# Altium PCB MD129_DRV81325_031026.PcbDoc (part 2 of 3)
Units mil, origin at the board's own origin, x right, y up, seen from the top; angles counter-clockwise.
Board outline 4300.91 x 4001.52 mil, 4 copper layers (Top Layer, GND, PWR, Bottom Layer), stack 92.668 mil thick; 211 components, 89 nets, 489 pads, 980 vias.
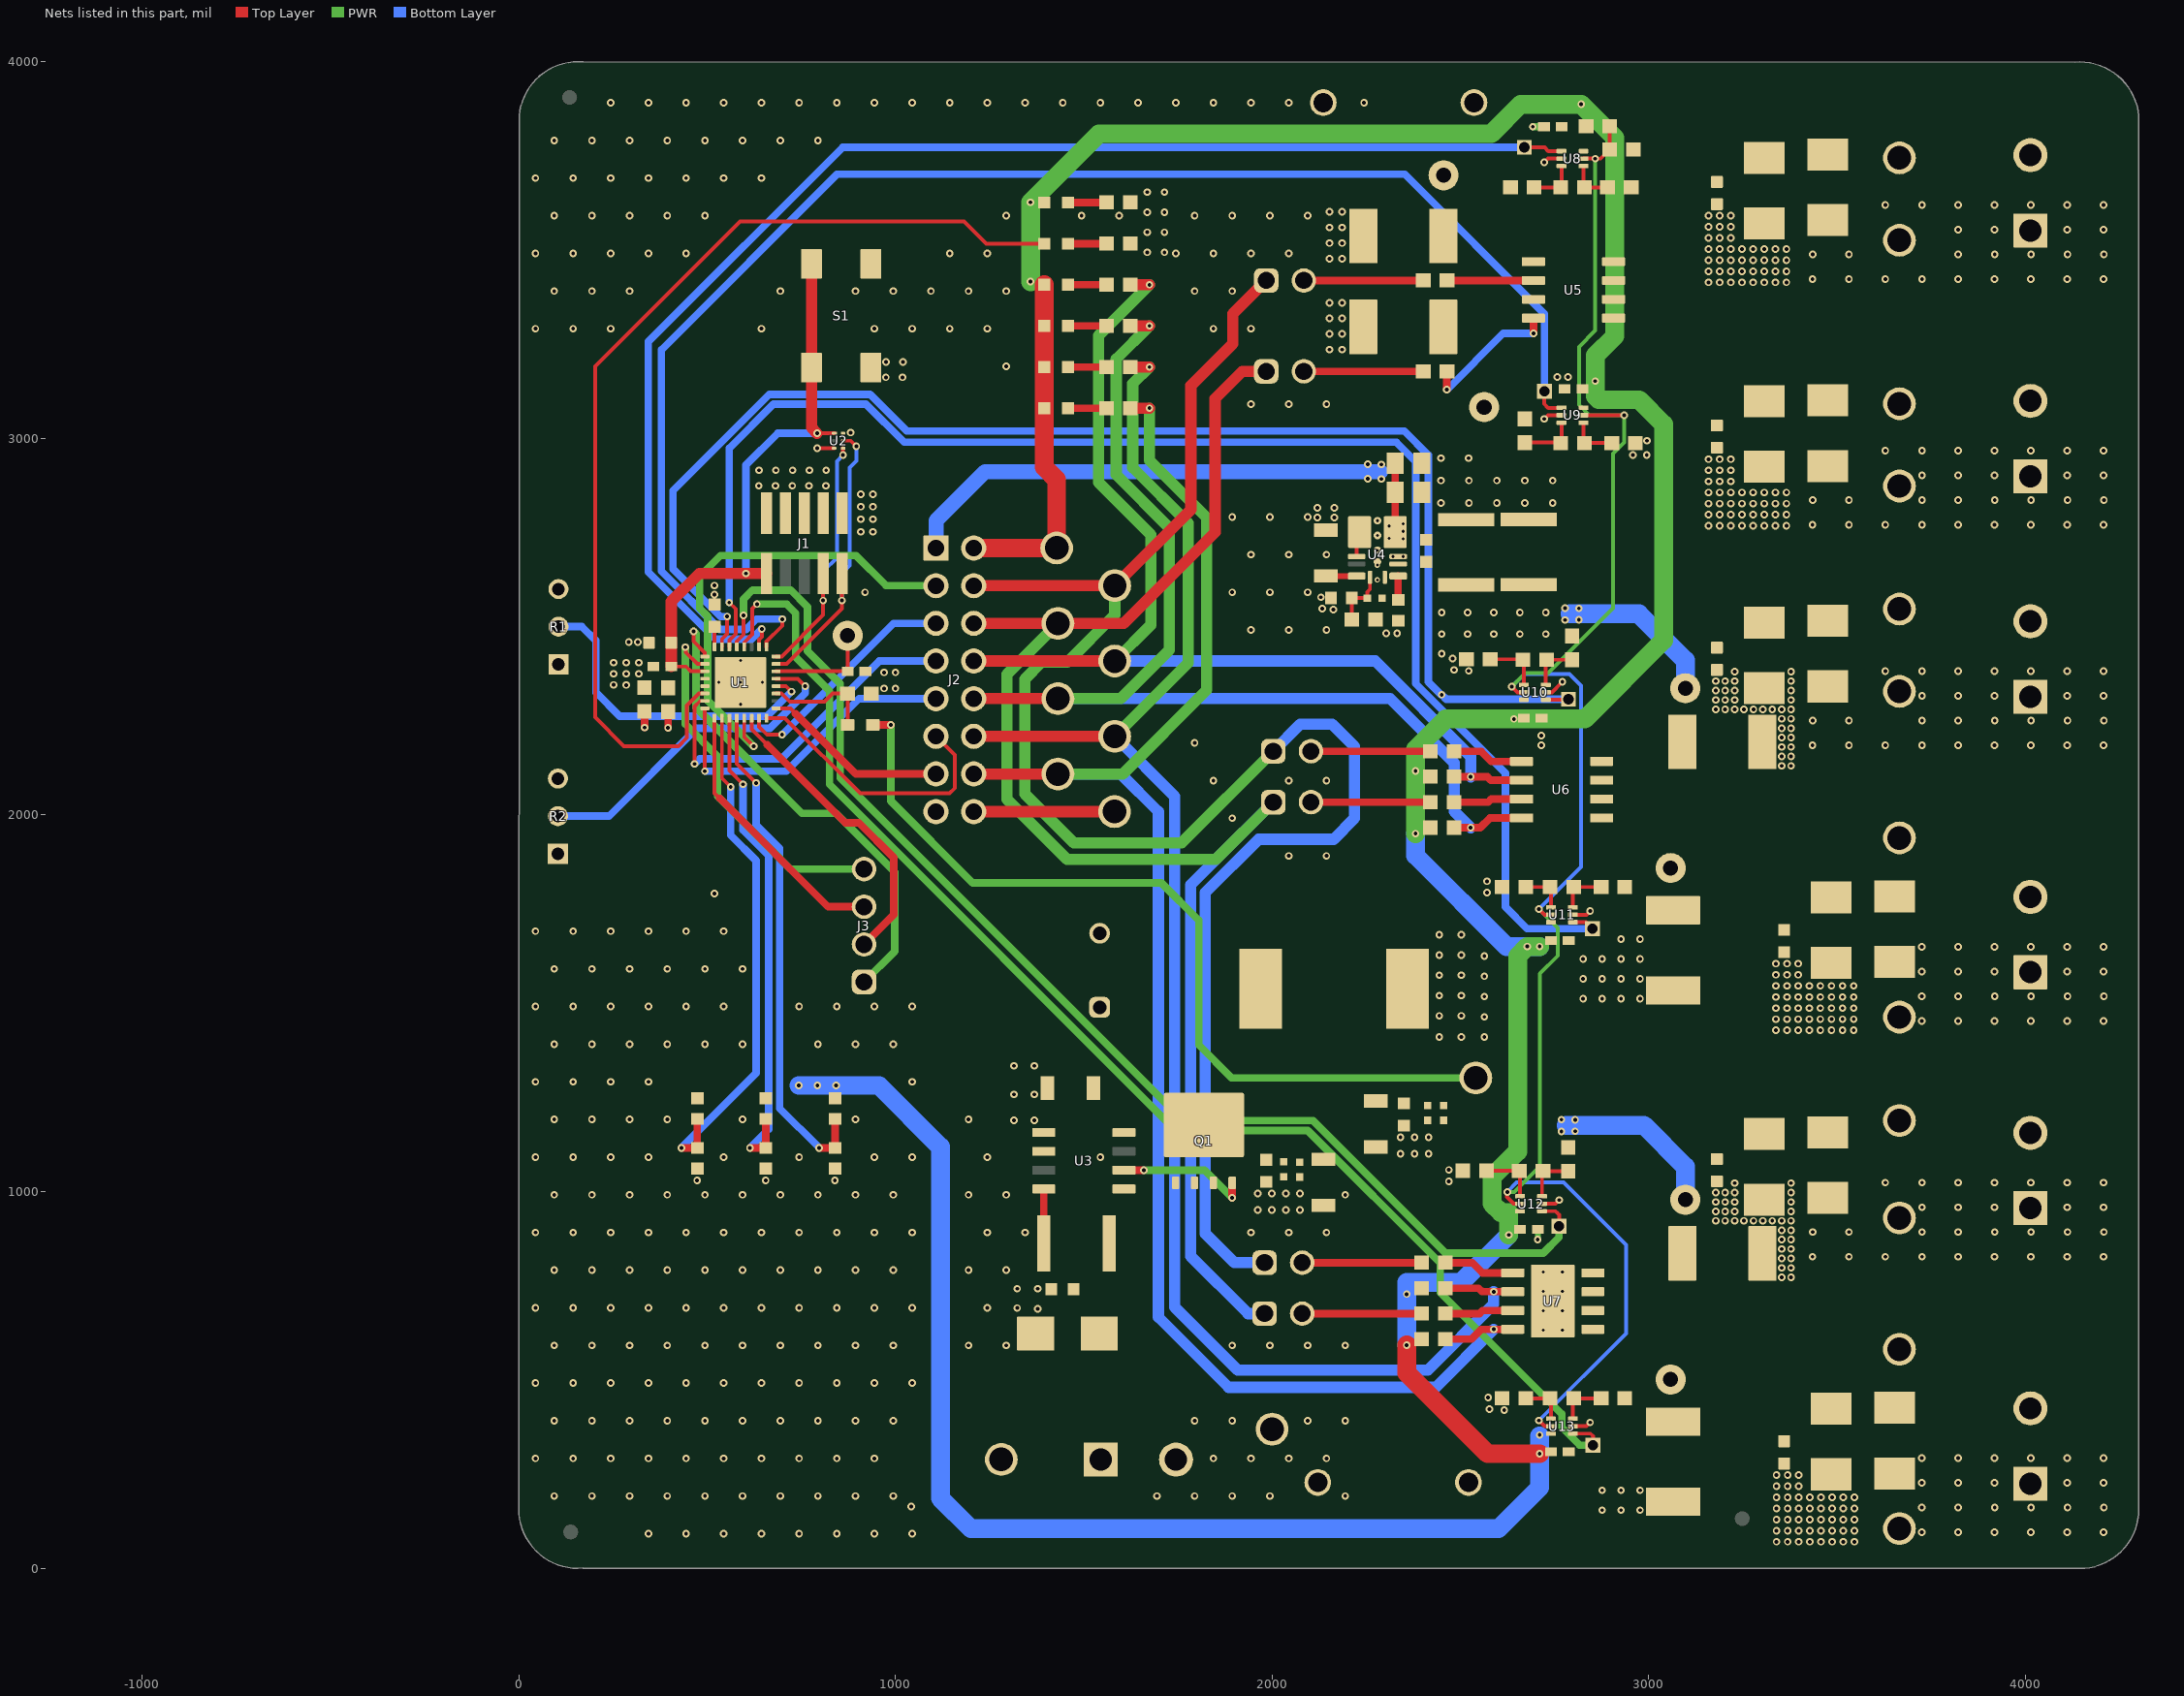
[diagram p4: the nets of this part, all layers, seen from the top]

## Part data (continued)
R14 R15 R16 R17 R18: library part CMP-0025912-5, "RES, 330, 5%, 0.1 W, 0603", Manufacturer=Yageo, Power_W=100mW, Supplier Part Number 1=311-330GRCT-ND, TempCo="100 ppm/C", Tolerance_%=5%, Value2=0.1W, Value_Code=330R, ValueDisplayed=330
R19 R20 R21 R22 R23 R24: library part CMP-0088493-1, "10 mOhms ±0.5% 2W Chip Resistor 2512 (6432 Metric) Automotive AEC-Q200, Current Sense, Moisture Resistant Metal Film", Digikey Part Number=273-PCS2512DR0100ETCT-ND, Manufacturer=Ohmite, Mouser Part Number=588-PCS2512DR0100ET, Operating Temperature Range="-55°C to +170°C", Power_W=2W, TempCo=50ppm/°C, Tolerance_%=0%
R25 R26: library part CMP-0022902-5, "RES, 200, 1%, 0.1 W, 0603", Manufacturer=Yageo, Power_W=100mW, Supplier Part Number 1=311-200HRCT-ND, TempCo="100 ppm/C", Tolerance_%=1%, Value2=0.1W, Value_Code=200R, ValueDisplayed=200
R27 R28 R31 R32 R36 R37 R42 R43 R44 R45 R50 R51: library part CMP-0025874-4, "RES, 0, 5%, 0.1 W, AEC-Q200 Grade 0, 0603", Manufacturer=Panasonic, Power_W=100mW, Supplier Part Number 1=P0.0GCT-ND, TempCo="600 ppm/C", Tolerance_%=5%, Value2=0.1W, Value_Code=0000, ValueDisplayed=0
R34: library part CMP-0022933-5, "RES, 23.2 k, 1%, 0.1 W, 0603", Manufacturer=Yageo, Power_W=100mW, Supplier Part Number 1=311-23.2KHRCT-ND, TempCo="100 ppm/C", Tolerance_%=1%, Value2=0.1W, Value_Code=23k2, ValueDisplayed=23.2k
R35: library part CMP-0025886-3, "RES, 10 k, 5%, 0.1 W, 0603", Manufacturer=Yageo, Power_W=100mW, Supplier Part Number 1=311-10KGRCT-ND, TempCo="100 ppm/C", Tolerance_%=5%, Value2=0.1W, Value_Code=10k0, ValueDisplayed=10k
R39 R41 R47 R49: library part CMP-0023155-5, "RES, 4.99 k, 1%, 0.1 W, 0603", Manufacturer=Yageo, Power_W=100mW, Supplier Part Number 1=311-4.99KHRCT-ND, TempCo="100 ppm/C", Tolerance_%=1%, Value2=0.1W, Value_Code=4k99, ValueDisplayed=4.99k
S1: library part CMP-0097347-1, "Tactile Switch SPST-NO Top Actuated Surface Mount", Coil Resistance_ohm=100mΩ, Contact Current Rating=50mA, Digikey Part Number=732-7022-1-ND, Manufacturer="Wurth Electronics", Mouser Part Number=710-430481025816, Operating Force=160gf, Operating Temperature Range="-40°C to +85°C"
SH1 SH2: library part CMP-0075110-1, "1mm Uninsulated Shorting Plug, 10.16mm spacing, TH", Manufacturer=Harwin, PartNumber=D3082-05, Supplier Part Number 1=952-1873-ND
SH1-J2-1 SH2-J2 SH3-J2 SH4-J2 SH5-J2 SH6-J2 SH7-J2 SH8-J2 SH-J5 SH-J6 SH-J7 SH-J8 SH-J9 SH-J10: library part CMP-0003761-2, "Shunt, 2.54mm, Gold, Black", Manufacturer="Wurth Elektronik", Supplier Part Number 1=732-2678-ND
TP1 TP12 TP13 TP14 TP15 TP17 TP18: library part CMP-0055139-2, "Test Point, Miniature, White, TH", Color=White, Manufacturer="Keystone Electronics", Supplier Part Number 1=36-5002-ND
TP2: library part CMP-0055150-1, "Test Point, Multipurpose, Orange, TH", Color=Orange, Manufacturer=Keystone, Supplier Part Number 1=36-5013-ND
TP3 TP4 TP5 TP6 TP7 TP8 TP19 TP21 TP23 TP25 TP27 TP29: library part CMP-0055149-2, "Test Point, Multipurpose, White, TH", Color=White, Manufacturer="Keystone Electronics", Supplier Part Number 1=36-5012-ND
TP9 TP11: library part CMP-0055148-2, "Test Point, Multipurpose, Black, TH", Color=Black, Manufacturer="Keystone Electronics", Supplier Part Number 1=36-5011-ND
TP10 TP16 TP20 TP22 TP24 TP26 TP28 TP30: library part CMP-0055147-2, "Test Point, Multipurpose, Red, TH", Color=Red, Manufacturer="Keystone Electronics", Supplier Part Number 1=36-5010-ND
U1: library part CMP-0093963-1, "Mixed-Signal Microcontrollers with CAN-FD Interface, VQFN32", Frequency_Fixed=80MHz, Manufacturer="Texas Instruments", Max Supply Voltage=3.6V, Min Supply Voltage=1.62V, Operating Temperature Range="-40°C to +125°C"
U2: library part CMP-0043115-2, "ESD-Protection Array for High-Speed Data Interfaces, 4 Channels, -40 to +85 degC, 6-pin SON (DRY), Green (RoHS & no Sb/Br)", Breakdown Voltage(Min)(V)=6, IO Capacitance(Typ)(pF)=1.6, IO Leakage Current(nA)=1, Manufacturer="Texas Instruments"
U3: library part CMP-0125797-1, Manufacturer="Texas Instruments", Operating Temperature Range=to, Part Number=LM74700D-Q1
U4: library part CMP-0094617-1, "3-V to 65-V Input, 1-V to 13-V Output, 600-mA Synchronous Buck Converter Power Module in a HotRod QFN Package", Manufacturer="Texas Instruments", Max Supply Voltage=65V, Min Supply Voltage=3.6V, Nominal Supply Current=17-18uA, Operating Temperature Range="-40°C to +125°C", Output Voltage=1-13V, Switching Frequency=200-2200kHz
U5: library part CMP-0127644-1, "Dual Channel Protected Low side switch, SOIC8", Manufacturer="Texas Instruments", Max Supply Voltage=5.5V, Min Supply Voltage=3V, Operating Temperature Range="-40°C to +150°C"
U6: library part CMP-0127803-1, Manufacturer="Texas Instruments", Operating Temperature Range=to
U7: library part CMP-0127624-1, "Dual Channel Protected Low side switch, HSOIC8", Manufacturer="Texas Instruments", Max Supply Voltage=5.5V, Min Supply Voltage=3V, Operating Temperature Range="-40°C to +150°C"
U8 U9 U10 U11 U12 U13: library part CMP-0085242-1, "Bidirectional, Precision Low- and High-Side Voltage Output, Current-Sense Amplifier, DRL0006A (SOT-5X3-6)", Alternate Manufacturer="Texas Instruments", Alternate PartNumber=INA185A2IDRLT
ZZ1: library part CMP-0003616-3
ZZ2: library part CMP-0077236-1
ZZ3: library part CMP-0077237-1
ZZ4: library part CMP-0077238-1

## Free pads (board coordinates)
  rect 39.37x39.37 hole 27.56: 7(2669.59,3772.78) 7(2722.57,3124.75) 7(2761.65,908.17) 7(2786.75,2307.25) 7(2850.31,1698.27) 7(2851.77,326.17)

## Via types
v1: diameter 20, hole 10, Top Layer to Bottom Layer, tented both sides, 955 vias
v2: diameter 19.68, hole 7.87, Top Layer to Bottom Layer, tented both sides, 16 vias
v3: diameter 19.68, hole 7.87, Top Layer to Bottom Layer, 5 vias
v4: diameter 14, hole 8, Top Layer to Bottom Layer, tented both sides, 4 vias

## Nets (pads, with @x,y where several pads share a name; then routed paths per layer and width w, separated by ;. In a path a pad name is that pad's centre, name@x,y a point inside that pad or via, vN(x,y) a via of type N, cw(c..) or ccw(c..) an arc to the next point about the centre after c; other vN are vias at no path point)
3V3: C24.2 C27.2 C30.2 C33.2 C36.2 C39.2 D1.2 D3.2 D4.2 D5.2 D6.2 J2.2 R7.1 R8.1 R9.1 R25.2 R39.1 R41.1 R47.1 R49.1 TP2.1 U8.6 U9.6 U10.6 U11.6 U12.6 U13.6 | length 10880.1
  Top Layer w50: J2.2@1207.37,2708.86 TP2.1@1427.69,2708.86 1427.69,2890.62 1394.69,2923.62 D6.2@1394.69,3080.28 D5.2@1394.69,3189.52 D4.2@1394.69,3298.75 D3.2@1394.69,3407.98 ; v1(2357.06,592.21) 2357.06,518.15 2571.52,303.69 v1(2709.96,303.69)
  PWR w50: v1(1358.33,3416.4) v1(1358.33,3627.1) 1540.24,3809.01 2581.43,3809.01 2659.7,3887.27 v1(2820.33,3887.27) 2909.62,3797.99 2909.62,3271.72 2857.73,3219.82 v1(2857.73,3151.98) 2857.73,3112.17 2867.4,3102.49 2974.02,3102.49 3038.9,3037.62 3038.9,2463.75 2830.2,2255.04 v1(2641.72,2255.04) 2460.64,2255.04 2380.43,2174.83 v1(2380.43,2116.98) v1(2380.43,1950.37) ; v1(2628.05,884.62) 2628.05,944.1 2607.38,944.1 2583.35,968.13 2583.35,1038.34 2651.48,1106.46 2651.48,1624.59 v1(2677.44,1650.55) v1(2709.96,1650.55)
  Bottom Layer w50: v1(743.05,1281.62) v1(792.65,1281.62) v1(842.25,1281.62) 956.02,1281.62 1119.17,1118.47 1119.17,185.67 1200.35,104.49 2600.62,104.49 2709.96,213.83 v1(2709.96,303.69) v1@2709.96,350.82 ; v1(2357.06,592.21) v1(2357.06,727.51) 2357.06,758.81 2502.24,758.81 v1(2628.05,884.62) ; v1(2380.43,1950.37) 2380.43,1892.37 2622.25,1650.55 v1(2677.44,1650.55) v1(2709.96,1650.55)
  other v1: 2709.96,353.43
BSL_INVOKE: R4.2 TP1.1 U1.22 | length 284.5
  Top Layer w10: U1.22@682.82,2381.47 R4.2@872.65,2381.47 TP1.1@872.65,2476.13
BUCK_3V3: C4.1 C5.1 C21.2 C22.1 C23.1 J1.1 J2.1 R1.1 R2.1 R3.2 R34.2 R35.2 U1.4 U2.6 U4.4 | length 1489.7
  Top Layer w20: U4.4@2326.57,2751.21 C22.1@2326.57,2857.12 C23.1@2326.57,2933.66
  Bottom Layer w40: J2.1@1107.37,2708.86 1107.37,2781.57 1237.75,2911.94 2287.88,2911.94
  other v1: 251.3,2345.44 284.7,2345.13 251.3,2374.74 284.7,2374.74 318.09,2374.74 251.3,2404.36 284.7,2404.36 318.09,2404.36 2302.75,2482.53 2331.64,2482.53 907.39,2751.91 939.99,2751.91 907.39,2785.26 939.99,2785.26 907.39,2818.61 939.99,2818.61 907.39,2851.95 939.99,2851.95 2289.83,2892.22 2253.92,2893.1 2253.92,2931.5 2289.83,2930.85 880.84,3015.56
  other v2: 2347.44,2733.49 2310.04,2735.07 2347.44,2753.18 2310.04,2767.35 2347.44,2772.86
DEV_ID1: R7.2 R10.1 U1.10 | length 1379.9
  Top Layer w10: U1.10@539.12,2257.46 539.12,2097.51 v1(562.1,2074.53)
  Top Layer w20: v1(431.48,1116.03) R10.1@473.51,1116.03 R7.2@473.51,1192.68
  Bottom Layer w20: v1(431.48,1116.03) 629.88,1314.42 629.88,1878.71 562.24,1946.35 562.24,2074.39 v1(562.1,2074.53)
DEV_ID2: R8.2 R11.1 U1.11 | length 1323.7
  Top Layer w10: U1.11@558.81,2257.46 558.81,2117.72 v1(595.14,2081.38)
  Top Layer w20: v1(613.46,1116.03) R11.1@655.49,1116.03 R8.2@655.49,1192.68
  Bottom Layer w20: v1(595.14,2081.38) 595.14,1960.11 662.91,1892.33 662.91,1165.48 v1(613.46,1116.03)
DEV_ID3: R9.2 R12.1 U1.12 | length 1350.7
  Top Layer w10: U1.12@578.49,2257.46 578.49,2136.36 v1(629.77,2085.08)
  Top Layer w20: v1(797.25,1116.03) R12.1@839.28,1116.03 R9.2@839.28,1192.68
  Bottom Layer w20: v1(629.77,2085.08) 629.77,1973.36 692.32,1910.82 692.32,1220.96 v1(797.25,1116.03)
GND: C1.1 C3.1 C4.2 C5.2 C6.1 C7.2 C8.1 C9.1 C10.1 C11.1 C12.1 C13.1 C14.1 C15.1 C16.2 C17.1 C18.1 C19.1 C20.1 C22.2 C23.2 C24.1 C26.1 C27.1 C29.1 C30.1 C32.1 C33.1 C35.1 C36.1 C38.1 C39.1 C41.1 D7.2 D8.1 D9.1 D10.1 D11.1 D12.1 D13.1 J1.3 J1.5 J1.7 J1.9 J2.15 J2.16 J4.2 R1.3 R2.3 R4.1 R5.1 R10.2 R11.2 R12.2 R13.1 R14.1 R19.1 R20.1 R21.1 R22.1 R23.1 R24.1 R26.1 R27.1 R32.1 R33.1 R36.1 R42.1 R44.1 R50.1 S1.3 S1.4 SH1.1 SH1.2 SH2.1 SH2.2 TP9.1 TP11.1 U1.5 U1.33 U2.3 U3.1 U4.10 U4.11 U7.9 U8.2 U9.2 U10.2 U11.2 U12.2 U13.2 | length 866.5
  Top Layer w10: v1(792.05,2974.11) U2.3@836.91,2974.11 ; U12.2@2716.35,967.51 2752.23,967.51 v1(2762.08,977.36) ; v1(2722.34,3051.64) 2732.19,3061.49 U9.2@2768.08,3061.49 ; v1(2722.34,3733.29) 2732.19,3743.14 U8.2@2768.08,3743.14 ; U10.2@2726.35,2325.67 2742.61,2325.67 v1(2770.34,2353.4) ; U13.2@2798.26,376.84 2834.14,376.84 v1(2843.99,386.69) ; U11.2@2798.26,1735 2834.14,1735 v1(2843.99,1744.86)
  Top Layer w20: v1(333.52,2232.07) C4.2@333.52,2275.37 ; v1(396.02,2231.37) C5.2@396.02,2274.67
  Top Layer w30: J2.16@1207.37,2008.86 TP9.1@1581.39,2008.86
  PWR w15: v1(2704.66,872.79) 2705.32,873.45 2705.32,899.15
  PWR w20: v1(2691.76,3827.65) 2691.97,3827.86 2721.49,3827.86
  other v1: 3339,69.96 3368.49,69.96 3397.98,69.96 3427.47,69.96 3456.96,69.96 3486.46,69.96 3515.95,69.96 3545.44,69.96 343.88,91.29 443.88,91.29 543.88,91.29 643.88,91.29 743.88,91.29 843.88,91.29 943.88,91.29 1043.88,91.29 3339,99.45 3368.49,99.45 3397.98,99.45 3427.47,99.45 3456.96,99.45 3486.46,99.45 3515.95,99.45 3545.44,99.45 3339,128.94 3368.49,128.94 3397.98,128.94 3427.47,128.94 3456.96,128.94 3486.46,128.94 3515.95,128.94 3545.44,128.94 2875.86,153.82 2926.18,153.82 2976.5,153.82 3339,158.43 3368.49,158.43 3397.98,158.43 3427.47,158.43 3456.96,158.43 3486.46,158.43 3515.95,158.43 3545.44,158.43 1041.59,163.28 3339,187.92 3368.49,187.92 3397.98,187.92 3427.47,187.92 3456.96,187.92 3486.46,187.92 3515.95,187.92 3545.44,187.92 93.88,191.29 193.88,191.29 293.88,191.29 393.88,191.29 493.88,191.29 593.88,191.29 693.88,191.29 793.88,191.29 893.88,191.29 993.88,191.29 1693.88,191.29 1793.88,191.29 1893.88,191.29 1993.88,191.29 2193.88,191.29 2875.86,206.6 2926.18,206.6 2976.5,206.6 3339,217.41 3368.49,217.41 3397.98,217.41 3339,246.9 3368.49,246.9 3397.98,246.9 43.88,291.29 143.88,291.29 243.88,291.29 343.88,291.29 443.88,291.29 543.88,291.29 643.88,291.29 743.88,291.29 843.88,291.29 943.88,291.29 1843.88,291.29 1943.88,291.29 2043.88,291.29 2143.88,291.29 93.88,391.29 193.88,391.29 293.88,391.29 393.88,391.29 493.88,391.29 593.88,391.29 693.88,391.29 793.88,391.29 893.88,391.29 993.88,391.29 1793.88,391.29 1893.88,391.29 2093.88,391.29 2193.88,391.29 2616.11,419.83 2576.89,422.23 2573.33,452.67 43.88,491.29 143.88,491.29 243.88,491.29 343.88,491.29 443.88,491.29 543.88,491.29 643.88,491.29 743.88,491.29 843.88,491.29 943.88,491.29 1043.88,491.29 93.88,591.29 193.88,591.29 293.88,591.29 393.88,591.29 493.88,591.29 593.88,591.29 693.88,591.29 793.88,591.29 893.88,591.29 993.88,591.29 1193.88,591.29 1293.88,591.29 1893.88,591.29 1993.88,591.29 2093.88,591.29 2193.88,591.29 1377.2,688.49 1322.98,690.63 43.88,691.29 143.88,691.29 243.88,691.29 343.88,691.29 443.88,691.29 543.88,691.29 643.88,691.29 743.88,691.29 843.88,691.29 943.88,691.29 1043.88,691.29 1243.88,691.29 1322.98,741.87 1377.2,741.87 3352.57,772.29 3377.57,772.29 93.88,791.29 193.88,791.29 293.88,791.29 393.88,791.29 493.88,791.29 593.88,791.29 693.88,791.29 793.88,791.29 893.88,791.29 993.88,791.29 1193.88,791.29 1293.88,791.29 3352.57,797.29 3377.57,797.29 3352.57,822.29 3377.57,822.29 3352.57,847.29 3377.57,847.29 3352.57,872.29 3377.57,872.29 43.88,891.29 143.88,891.29 243.88,891.29 343.88,891.29 443.88,891.29 543.88,891.29 643.88,891.29 743.88,891.29 843.88,891.29 943.88,891.29 1043.88,891.29 1243.88,891.29 1343.88,891.29 1943.88,891.29 2043.88,891.29 2143.88,891.29 3352.57,897.29 3377.57,897.29 3177.57,922.29 3202.57,922.29 3227.57,922.29 3252.57,922.29 3277.57,922.29 3302.57,922.29 3327.57,922.29 3352.57,922.29 3377.57,922.29 3177.57,947.29 3202.57,947.29 3227.57,947.29 3377.57,947.29 1961.68,950.69 1999.04,950.69 2036.41,950.69 2073.77,950.69 3177.57,972.29 3202.57,972.29 3227.57,972.29 3377.57,972.29 93.88,991.29 193.88,991.29 293.88,991.29 393.88,991.29 493.88,991.29 593.88,991.29 693.88,991.29 793.88,991.29 893.88,991.29 993.88,991.29 1193.88,991.29 1293.88,991.29 2193.88,991.29 1961.68,994.66 1999.04,994.66 2036.41,994.66 2073.77,994.66 3177.57,997.29 3202.57,997.29 3227.57,997.29 3377.57,997.29 3227.57,1022.29 3377.57,1022.29 2469.05,1026.93 473.13,1029.15 655.11,1029.15 838.9,1029.15 2469.05,1057.38 43.88,1091.29 143.88,1091.29 243.88,1091.29 343.88,1091.29 543.88,1091.29 743.88,1091.29 943.88,1091.29 1043.88,1091.29 1243.88,1091.29 1543.88,1091.29 2340.65,1100.33 2378.01,1100.33 2415.38,1100.33 2340.65,1144.3 2378.01,1144.3 2415.38,1144.3 1314.24,1189.22 1368.12,1189.22 93.88,1191.29 193.88,1191.29 293.88,1191.29 393.88,1191.29 593.88,1191.29 893.88,1191.29 1193.88,1191.29 1314.24,1257.95 1368.12,1257.95 43.88,1291.29 143.88,1291.29 243.88,1291.29 343.88,1291.29 1043.88,1291.29 1314.24,1333.69 1368.12,1333.69 93.88,1391.29 193.88,1391.29 293.88,1391.29 393.88,1391.29 493.88,1391.29 593.88,1391.29 793.88,1391.29 893.88,1391.29 993.88,1391.29 3337.32,1428.12 3366.81,1428.12 3396.31,1428.12 3425.8,1428.12 3455.29,1428.12 3484.78,1428.12 3514.27,1428.12 3543.76,1428.12 3337.32,1457.61 3366.81,1457.61 3396.31,1457.61 3425.8,1457.61 3455.29,1457.61 3484.78,1457.61 3514.27,1457.61 3543.76,1457.61 3337.32,1487.1 3366.81,1487.1 3396.31,1487.1 3425.8,1487.1 3455.29,1487.1 3484.78,1487.1 3514.27,1487.1 3543.76,1487.1 43.88,1491.29 143.88,1491.29 243.88,1491.29 343.88,1491.29 443.88,1491.29 543.88,1491.29 743.88,1491.29 843.88,1491.29 943.88,1491.29 1043.88,1491.29 2825.55,1511.98 2875.86,1511.98 2926.18,1511.98 2976.5,1511.98 3337.32,1516.59 3366.81,1516.59 3396.31,1516.59 3425.8,1516.59 3455.29,1516.59 3484.78,1516.59 3514.27,1516.59 3543.76,1516.59 3337.32,1546.08 3366.81,1546.08 3396.31,1546.08 3425.8,1546.08 3455.29,1546.08 3484.78,1546.08 3514.27,1546.08 3543.76,1546.08 2825.55,1564.76 2875.86,1564.76 2926.18,1564.76 2976.5,1564.76 3337.32,1575.57 3366.81,1575.57 3396.31,1575.57 93.88,1591.29 193.88,1591.29 293.88,1591.29 393.88,1591.29 493.88,1591.29 593.88,1591.29 3337.32,1605.06 3366.81,1605.06 3396.31,1605.06 2825.55,1617.54 2875.86,1617.54 2926.18,1617.54 2976.5,1617.54 2926.18,1670.32 2976.5,1670.32 43.88,1691.29 143.88,1691.29 243.88,1691.29 343.88,1691.29 443.88,1691.29 543.88,1691.29 518.88,1791.29 2570.65,1793.95 2570.65,1823.95 2043.88,1891.29 2143.88,1891.29 1893.88,1991.29 1843.88,2091.29 2043.88,2091.29 2143.88,2091.29 3352.57,2130.45 3377.57,2130.45 3352.57,2155.45 3377.57,2155.45 3352.57,2180.45 3377.57,2180.45 2714.66,2184.85 1793.88,2191.29 3352.57,2205.45 3377.57,2205.45 2714.66,2210.96 3352.57,2230.45 3377.57,2230.45 3352.57,2255.45 3377.57,2255.45 3177.57,2280.45 3202.57,2280.45 3227.57,2280.45 3252.57,2280.45 3277.57,2280.45 3302.57,2280.45 3327.57,2280.45 3352.57,2280.45 3377.57,2280.45 3177.57,2305.45 3202.57,2305.45 3227.57,2305.45 3377.57,2305.45 3177.57,2330.45 3202.57,2330.45 3227.57,2330.45 3377.57,2330.45 969.68,2336.06 999.78,2336.06 3177.57,2355.45 3202.57,2355.45 3227.57,2355.45 3377.57,2355.45 969.68,2378.45 999.78,2378.45 3227.57,2380.45 3377.57,2380.45 2521.83,2382.71 2482.61,2385.1 2479.05,2415.55 2450.06,2428.53 291.78,2459.02 315.83,2459.02 1943.88,2491.29 2043.88,2491.29 2143.88,2491.29 2162.06,2545.34 2132.84,2547.73 2129.28,2578.18 519.21,2585.27 918.88,2591.29 1893.88,2591.29 1993.88,2591.29 2093.88,2591.29 519.21,2609.32 1943.88,2691.29 2043.88,2691.29 2143.88,2691.29 3158.7,2767.85 3188.19,2767.85 3217.68,2767.85 3247.17,2767.85 3276.66,2767.85 3306.15,2767.85 3335.64,2767.85 3365.13,2767.85 2120.06,2789.74 2165.01,2789.74 1893.88,2791.29 1993.88,2791.29 2093.88,2791.29 3158.7,2797.34 3188.19,2797.34 3217.68,2797.34 3247.17,2797.34 3276.66,2797.34 3306.15,2797.34 3335.64,2797.34 3365.13,2797.34 2120.06,2815.68 2165.01,2815.68 3158.7,2826.83 3188.19,2826.83 3217.68,2826.83 3247.17,2826.83 3276.66,2826.83 3306.15,2826.83 3335.64,2826.83 3365.13,2826.83 2448.14,2828.64 2522.29,2828.64 2596.43,2828.64 2670.57,2828.64 2744.72,2828.64 3158.7,2856.32 3188.19,2856.32 3217.68,2856.32 3247.17,2856.32 3276.66,2856.32 3306.15,2856.32 3335.64,2856.32 3365.13,2856.32 636.94,2874.26 681.41,2874.26 725.88,2874.26 770.34,2874.26 814.81,2874.26 3158.7,2885.81 3188.19,2885.81 3217.68,2885.81 2448.14,2888.07 2522.29,2888.07 2596.43,2888.07 2670.57,2888.07 2744.72,2888.07 637.64,2915.24 682.16,2915.24 726.69,2915.24 771.22,2915.24 815.75,2915.24 3158.7,2915.3 3188.19,2915.3 3217.68,2915.3 3158.7,2944.79 3188.19,2944.79 3217.68,2944.79 2448.14,2947.5 2521.45,2947.5 2957.65,2955.78 2994.28,2955.78 2994.95,2993.71 1943.88,3091.29 2043.88,3091.29 2143.88,3091.29 974.22,3162.26 1018.69,3162.26 2757.06,3162.73 2785.51,3162.73 1293.88,3191.29 974.91,3203.23 1019.44,3203.23 2152.07,3235.81 2185.26,3235.81 2152.07,3277.3 2185.26,3277.3 43.88,3291.29 143.88,3291.29 243.88,3291.29 643.88,3291.29 943.88,3291.29 1043.88,3291.29 1143.88,3291.29 1243.88,3291.29 1843.88,3291.29 1943.88,3291.29 2152.07,3318.79 2185.26,3318.79 2152.07,3360.27 2185.26,3360.27 93.88,3391.29 193.88,3391.29 293.88,3391.29 693.88,3391.29 893.88,3391.29 993.88,3391.29 1093.88,3391.29 1193.88,3391.29 1293.88,3391.29 1793.88,3391.29 1893.88,3391.29 3158.7,3414.42 3188.19,3414.42 3217.68,3414.42 3247.17,3414.42 3276.66,3414.42 3306.15,3414.42 3335.64,3414.42 3365.13,3414.42 3158.7,3443.91 3188.19,3443.91 3217.68,3443.91 3247.17,3443.91 3276.66,3443.91 3306.15,3443.91 3335.64,3443.91 3365.13,3443.91 3158.7,3473.4 3188.19,3473.4 3217.68,3473.4 3247.17,3473.4 3276.66,3473.4 3306.15,3473.4 3335.64,3473.4 3365.13,3473.4 2152.07,3477.11 2185.26,3477.11 43.88,3491.29 143.88,3491.29 243.88,3491.29 343.88,3491.29 443.88,3491.29 1143.88,3491.29 1243.88,3491.29 1743.88,3491.29 1843.88,3491.29 1943.88,3491.29 2043.88,3491.29 1667.94,3494.19 1713.95,3494.19 3158.7,3502.89 3188.19,3502.89 3217.68,3502.89 3247.17,3502.89 3276.66,3502.89 3306.15,3502.89 3335.64,3502.89 3365.13,3502.89 2152.07,3518.6 2185.26,3518.6 3158.7,3532.38 3188.19,3532.38 3217.68,3532.38 1667.94,3547.47 1713.95,3547.47 2152.07,3560.09 2185.26,3560.09 3158.7,3561.87 3188.19,3561.87 3217.68,3561.87 93.88,3591.29 193.88,3591.29 293.88,3591.29 393.88,3591.29 493.88,3591.29 1293.88,3591.29 1493.88,3591.29 1593.88,3591.29 1793.88,3591.29 1893.88,3591.29 1993.88,3591.29 2093.88,3591.29 3158.7,3591.36 3188.19,3591.36 3217.68,3591.36 1667.94,3600.74 1713.95,3600.74 2152.07,3601.57 2185.26,3601.57 1667.94,3654.01 1713.95,3654.01 43.88,3691.29 143.88,3691.29 243.88,3691.29 343.88,3691.29 443.88,3691.29 543.88,3691.29 643.88,3691.29 93.88,3791.29 193.88,3791.29 293.88,3791.29 393.88,3791.29 493.88,3791.29 593.88,3791.29 693.88,3791.29 793.88,3791.29 243.88,3891.29 343.88,3891.29 443.88,3891.29 543.88,3891.29 643.88,3891.29 743.88,3891.29 843.88,3891.29 943.88,3891.29 1043.88,3891.29 1143.88,3891.29 1243.88,3891.29 1343.88,3891.29 1443.88,3891.29 1543.88,3891.29 1643.88,3891.29 1743.88,3891.29 1843.88,3891.29 1943.88,3891.29 2043.88,3891.29 2243.88,3891.29
  other v2: 2719.25,632.22 2770.43,632.22 2719.25,683.4 2770.43,683.4 2719.25,734.58 2770.43,734.58 2719.25,785.77 2770.43,785.77 2279.33,2702.78 2279.33,2742.15 2279.33,2781.52
  other v3: 588.33,2293.88 530.26,2351.95 588.33,2351.95 646.4,2351.95 588.33,2410.02
  other v4: 2279.33,2624.04 2279.33,2663.41
IN1: J2.4 J5.1 J7.1 J9.1 TP3.1 | length 4891.2
  Top Layer w30: J2.4@1207.37,2608.86 TP3.1@1581.99,2608.86 1784.2,2811.07 1784.2,3140.11 1895.66,3251.57 1895.66,3331.02 J5.1@1983.96,3419.31
  PWR w30: TP3.1@1581.99,2608.86 1581.99,2531.72 1456.06,2405.8 1387.61,2405.8 1342.94,2361.12 1342.94,2055.98 1473.16,1925.77 1759.45,1925.77 J7.1@2002.92,2169.23
  Bottom Layer w30: J9.1@1979.54,811.07 1899.48,811.07 1822.42,888.13 1822.42,1793.91 1963.74,1935.23 2162.59,1935.23 2218.47,1991.11 2218.47,2181.6 2159.17,2240.91 2074.59,2240.91 J7.1@2002.92,2169.23
IN1_U1_D: R29.2 U5.2 | length 229.8
  Top Layer w20: R29.2@2463.83,3419.31 U5.2@2693.63,3419.31
IN1_U2_AD: R38.2 U6.1 | length 190.3
  Top Layer w20: R38.2@2482.79,2169.23 2554.54,2169.23 2581.62,2142.16 U6.1@2661.92,2142.16
IN1_U3_ADDA: R46.2 U7.1 | length 190.3
  Top Layer w20: R46.2@2459.41,811.07 2531.16,811.07 2558.24,783.99 U7.1@2638.54,783.99
IN2: J2.6 J6.1 J8.1 J10.1 TP4.1 | length 4177.6
  Top Layer w30: J2.6@1207.37,2508.86 TP4.1@1431.11,2508.86 1606.19,2508.86 1848.33,2751 1848.33,3106.05 1920.37,3178.08 J6.1@1983.96,3178.08
  PWR w30: TP4.1@1431.11,2508.86 1295.69,2373.44 1295.69,2041.54 1455.54,1881.7 1850.69,1881.7 J8.1@2002.92,2033.94
  Bottom Layer w30: J10.1@1979.54,675.77 1935.82,675.77 1783.44,828.15 1783.44,1814.46 J8.1@2002.92,2033.94
IN2_U1_D: R30.2 U5.4 | length 380.7
  Top Layer w20: v1(2463.83,3129.35) R30.2@2463.83,3178.08 ; v1(2693.63,3279.16) U5.4@2693.63,3319.31
  Bottom Layer w20: v1(2463.83,3129.35) 2613.65,3279.16 v1(2693.63,3279.16)
IN2_U2_AD: R40.2 U6.3 | length 182.5
  Top Layer w20: R40.2@2482.79,2033.94 2573.54,2033.94 2581.76,2042.16 U6.3@2661.92,2042.16
IN2_U3_ADDA: R48.2 U7.3 | length 182.5
  Top Layer w20: R48.2@2459.41,675.77 2550.16,675.77 2558.38,683.99 U7.3@2638.54,683.99
INA_REF: R25.1 R26.2 U8.5 U9.5 U10.5 U11.5 U12.5 U13.5 | length 4750.4
  Top Layer w10: v1(2624.35,998.45) 2623.09,998.45 2623.09,985.63 2641.21,967.51 U12.5@2658.08,967.51 ; v1(2636.27,2340.61) 2651.21,2325.67 U10.5@2668.08,2325.67 ; v1(2708.18,391.78) 2723.12,376.84 U13.5@2739.99,376.84 ; v1(2708.18,1749.94) 2723.12,1735 U11.5@2739.99,1735 ; U9.5@2826.35,3061.49 v1(2934.48,3061.49) ; U8.5@2826.35,3743.14 2857.5,3743.14 v1(2857.75,3742.89) 2871.72,3742.89 R26.2@2896.11,3767.28 R25.1@2896.11,3829.1
  PWR w10: v1(2624.35,998.45) 2642.27,998.45 2710.81,1066.99 2710.81,1578.47 2758.16,1625.82 2758.16,1699.96 v1(2708.18,1749.94) ; v1(2636.27,2340.61) 2672.29,2376.63 2731.99,2376.63 2904.83,2549.47 2904.83,2959.87 2934.48,2989.52 v1(2934.48,3061.49) 2842.1,3061.49 2814.6,3088.99 2814.6,3243.2 2857.75,3286.36 v1(2857.75,3742.89)
  Bottom Layer w10: v1(2624.35,998.45) 2623.72,999.08 2648.92,1024.28 2774.03,1024.28 2939.63,858.68 2939.63,623.23 v1(2708.18,391.78) ; v1(2636.27,2340.61) 2670.06,2374.4 2789.56,2374.4 2820.16,2343.8 2820.16,1861.92 v1(2708.18,1749.94)
MCU_STATUS: D2.2 U1.6 | length 2739.1
  Top Layer w10: U1.6@493.85,2322.42 477.79,2322.42 445.58,2290.2 445.58,2205 423.36,2182.78 278.72,2182.78 202.08,2259.42 202.08,3190.88 587.05,3575.86 1181.99,3575.86 1240.64,3517.21 D2.2@1394.69,3517.21
NetC2_1: C2.1 U3.4 | length 144.3
  Top Layer w20: C2.1@1393.77,862.45 U3.4@1393.77,1006.79
NetC6_2: C6.2 U1.32 | length 53.3
  Top Layer w10: U1.32@519.44,2446.43 C6.2@519.44,2499.7
NetC20_2: C20.2 U4.8 | length 81.7
  Top Layer w15: C20.2@2142.5,2634.6 U4.8@2224.21,2634.6
NetC21_1: C21.1 R33.2 R34.1 U4.9 | length 156.5
  Top Layer w10: R34.1@2211.28,2518.77 R33.2@2211.28,2576.02 C21.1@2252.45,2576.02 2252.45,2592.12 2259.65,2599.31 U4.9@2259.65,2631.13
NetD1_1: D1.1 R13.2 | length 102.6
  Top Layer w20: D1.1@1457.68,3626.44 R13.2@1560.29,3626.44
NetD2_1: D2.1 R14.2 | length 102.6
  Top Layer w20: D2.1@1457.68,3517.21 R14.2@1560.29,3517.21
NetD3_1: D3.1 R15.2 | length 102.6
  Top Layer w20: D3.1@1457.68,3407.98 R15.2@1560.29,3407.98
NetD4_1: D4.1 R16.2 | length 102.6
  Top Layer w20: D4.1@1457.68,3298.75 R16.2@1560.29,3298.75
NetD5_1: D5.1 R17.2 | length 102.6
  Top Layer w20: D5.1@1457.68,3189.52 R17.2@1560.29,3189.52
NetD6_1: D6.1 R18.2 | length 102.6
  Top Layer w20: D6.1@1457.68,3080.28 R18.2@1560.29,3080.28
NetJ5_2: J5.2 R29.1 | length 316.9
  Top Layer w20: J5.2@2083.96,3419.31 R29.1@2400.84,3419.31
NetJ6_2: J6.2 R30.1 | length 316.9
  Top Layer w20: J6.2@2083.96,3178.08 R30.1@2400.84,3178.08
NetJ7_2: J7.2 R38.1 | length 316.9
  Top Layer w20: J7.2@2102.92,2169.23 R38.1@2419.8,2169.23
NetJ8_2: J8.2 R40.1 | length 316.9
  Top Layer w20: J8.2@2102.92,2033.94 R40.1@2419.8,2033.94
NetJ9_2: J9.2 R46.1 | length 316.9
  Top Layer w20: J9.2@2079.54,811.07 R46.1@2396.42,811.07
NetJ10_2: J10.2 R48.1 | length 316.9
  Top Layer w20: J10.2@2079.54,675.77 R48.1@2396.42,675.77
NetQ1_4: Q1.4 U3.6 | length 357.5
  Top Layer w20: U3.6@1606.37,1056.79 v1(1659.27,1056.79) ; v1(1893.73,983.3) Q1.4@1893.73,1022.95
  PWR w20: v1(1659.27,1056.79) 1820.23,1056.79 v1(1893.73,983.3)
NetR35_1: R35.1 U4.1 | length 63.8
  Top Layer w20: R35.1@2334.45,2570.82 U4.1@2334.45,2634.6
NetU4_5: U4.5 U4.6 | length 68.2
  Top Layer w10: U4.6@2224.21,2686.25 2224.21,2743.34 U4.5@2232.09,2751.21
nRST: C16.1 J1.10 R3.1 S1.1 S1.2 U1.3 U2.1 | length 1550.8
  Top Layer w10: R3.1@419.4,2394.13 443.78,2394.13 456.44,2381.47 U1.3@493.85,2381.47 ; v1(791.62,3013.48) U2.1@837.89,3013.48
  Top Layer w30: R3.1@404.4,2394.13 C16.1@404.4,2457.28 404.4,2566.46 479.31,2641.37 v1(602.64,2641.37) J1.10@657.77,2641.37 ; S1.2@776.89,3463.65 S1.1@776.89,3188.06 776.89,3028.21 v1(791.62,3013.48)
  Bottom Layer w20: v1(602.64,2641.37) 602.64,2929.39 686.74,3013.48 v1(791.62,3013.48)
OUT1_U1_D: C26.2 D8.2 D14.2 J11.2 TP19.1 U5.7 U5.8
OUT1_U2_AD: C32.2 D10.2 D16.2 J13.2 TP23.1 U6.8
OUT1_U3_ADDA: C38.2 D12.2 D18.2 J15.2 TP27.1 U7.8
OUT2_U1_D: C29.2 D9.2 D15.2 J12.2 TP21.1 U5.5 U5.6
OUT2_U2_AD: C35.2 D11.2 D17.2 J14.2 TP25.1 U6.6
OUT2_U3_ADDA: C41.2 D13.2 D19.2 J16.2 TP29.1 U7.6
PA0_GPIO_AUX: J3.1 U1.1 | length 1318.6
  Top Layer w10: v1(463.62,2487.65) 463.62,2461.12 493.85,2430.89 U1.1@493.85,2420.84
  PWR w20: v1(463.62,2487.65) 470.26,2481.01 470.26,2285.43 751.63,2004.07 841.94,2004.07 997.81,1848.2 997.81,1637.84 J3.1@916.27,1556.29
PA1_GPIO_AUX: J3.4 U1.2 | length 977.6
  Top Layer w10: v1(442.06,2445.57) 443.41,2444.22 443.41,2431.56 473.8,2401.16 U1.2@493.85,2401.16
  PWR w20: v1(442.06,2445.57) 442.06,2241.22 527.65,2155.64 527.65,2049.84 721.2,1856.29 J3.4@916.27,1856.29
PA5_GPIO_AUX: J3.3 U1.9 | length 721.2
  Top Layer w10: U1.9@519.44,2257.46 519.44,2058.05 533.59,2043.9
  Top Layer w20: 533.59,2043.9 821.2,1756.29 J3.3@916.27,1756.29
PA10_GPIO_AUX: J3.2 U1.14 | length 811.2
  Top Layer w10: U1.14@617.86,2257.46 617.86,2227.93 659.11,2186.69
  Top Layer w20: 659.11,2186.69 866.31,1979.48 902.18,1979.48 995.22,1886.44 995.22,1735.25 J3.2@916.27,1656.29
PI_IN: C3.2 C7.1 C8.2 C9.2 C10.2 C11.2 L1.1 Q1.5 Q1.6 Q1.7 Q1.8 Q1.9@1818.73,1176.49 U3.8
POT_IN1: R1.2 U1.20 | length 870.9
  Top Layer w10: U1.20@682.82,2342.1 708.79,2342.1 v1(723.46,2327.43)
  Bottom Layer w20: R1.2@105.09,2500.02 167.39,2500.02 204.55,2462.86 204.55,2325.56 267.76,2262.34 658.38,2262.34 v1(723.46,2327.43)
POT_IN2: R2.2 U1.21 | length 896.1
  Top Layer w10: U1.21@682.82,2361.79 740.78,2361.79 v1(760.17,2342.4)
  Bottom Layer w20: R2.2@103.57,1996.85 239.33,1996.85 472.47,2229.99 666.59,2229.99 760.17,2323.58 v1(760.17,2342.4)
PWM_IN1: J2.3 U1.13 | length 1279.8
  Top Layer w10: U1.13@598.18,2257.46 598.18,2207.28 v1(623.09,2182.37)
  PWR w20: v1(623.09,2182.37) 622.47,2182.37 501.07,2303.77 501.07,2527.33 480.04,2548.36 480.04,2633.81 535.15,2688.92 894.91,2688.92 974.97,2608.86 J2.3@1107.37,2608.86
PWM_IN2: J2.5 U1.15 | length 624.3
  Top Layer w10: U1.15@637.55,2257.46 637.55,2234.34 658.79,2213.1 v1(698.7,2213.1)
  Bottom Layer w20: v1(698.7,2213.1) 994.45,2508.86 J2.5@1107.37,2508.86
SRC1_U1_D: R19.2 R28.1 TP12.1 U5.1
SRC1_U1_D_MCU: pad.7@2669.59,3772.78 U1.26 U8.1 | length 3690.5
  Top Layer w10: U1.26@637.55,2446.43 637.55,2465.55 644.75,2472.76 v1(644.75,2493.85) ; pad.7@2669.59,3772.78 2723,3772.78 2732.95,3762.83 U8.1@2768.08,3762.83
  Bottom Layer w20: v1(644.75,2493.85) 617.5,2466.6 522.4,2466.6 343.73,2645.27 343.73,3256.91 859.59,3772.78 pad.7@2669.59,3772.78
SRC1_U1_IN_N: C25.2 R27.2 U8.4 | length 119.6
  Top Layer w10: U8.4@2826.35,3723.46 2826.35,3668.75 C25.2@2828.64,3666.46 ; C25.2@2828.71,3666.39 R27.2@2890.33,3666.39
SRC1_U1_IN_P: C25.1 R28.2 U8.3 | length 128.4
  Top Layer w10: R28.2@2695.34,3666.39 C25.1@2765.72,3666.39 2768.08,3668.75 U8.3@2768.08,3723.46
SRC1_U2_AD: R21.2 R37.1 TP14.1 U6.7 | length 431.8
  Bottom Layer w50: 2790.36,2534 2973.42,2534 3096.94,2410.48 TP14.1@3096.94,2336.38
  other v1: 2777.83,2517.65 2814.06,2518.41 2814.06,2548.71 2777.83,2549.28
SRC1_U2_AD_MCU: pad.7@2786.75,2307.25 U1.31 U10.1 | length 3722.5
  Top Layer w10: U1.31@539.12,2446.43 539.12,2466.95 552.92,2480.74 v1(552.92,2526.99) ; U10.1@2726.35,2305.99 2785.49,2305.99 pad.7@2786.75,2307.25
  Bottom Layer w20: v1(552.92,2526.99) 535.55,2526.99 409.19,2653.35 409.19,2861.22 665.04,3117.07 932.26,3117.07 1029.9,3019.44 2350.92,3019.44 2414.37,2955.99 2414.37,2353.79 v1@2449.46,2318.7 ; v1(2450.06,2319.3) 2462.11,2307.25 pad.7@2786.75,2307.25
SRC1_U2_IN_N: C31.2 R36.2 U10.4 | length 155.1
  Top Layer w10: R36.2@2578.92,2413.39 2664.56,2413.39 C31.2@2665.72,2412.23 2668.08,2409.87 U10.4@2668.08,2345.36
SRC1_U2_IN_P: C31.1 R37.2 U10.3 | length 135.5
  Top Layer w10: U10.3@2726.35,2345.36 2726.35,2409.87 C31.1@2728.71,2412.23 R37.2@2796.34,2412.23
SRC1_U3_ADDA: R23.2 R45.1 TP17.1 U7.7 | length 449.8
  Bottom Layer w50: 2780.36,1175.84 2987.06,1175.84 3096.94,1065.96 TP17.1@3096.94,978.22
  other v1: 2767.83,1159.48 2804.06,1160.25 2804.06,1190.55 2767.83,1191.12
SRC1_U3_ADDA_MCU: pad.7@2761.65,908.17 U1.29 U12.1 | length 3387.1
  Top Layer w10: U1.29@578.49,2446.43 578.49,2461.06 596.81,2479.38 596.27,2479.92 v1(596.27,2530) ; U12.1@2716.35,947.83 2751.48,947.83 2761.43,937.88 ; 2756.45,942.85 2761.43,937.88 ; pad.7@2761.65,908.17 2761.65,937.66 2761.43,937.88
  PWR w20: v1(596.27,2530) 596.27,2572.89 620.48,2597.1 721.8,2597.1 766.18,2552.72 766.18,2435.07 852.78,2348.47 852.78,2098.83 1763.43,1188.19 2108.35,1188.19 2459.96,836.57 2719.63,836.57 2761.65,878.6 pad.7@2761.65,908.17
SRC1_U3_IN_N: C37.2 R44.2 U12.4 | length 155.1
  Top Layer w10: R44.2@2568.92,1055.22 2654.56,1055.22 C37.2@2655.72,1054.06 2658.08,1051.7 U12.4@2658.08,987.2
SRC1_U3_IN_P: C37.1 R45.2 U12.3 | length 135.5
  Top Layer w10: U12.3@2716.35,987.2 2716.35,1051.7 C37.1@2718.71,1054.06 R45.2@2786.34,1054.06
SRC2_U1_D: R20.2 R31.1 TP13.1 U5.3
SRC2_U1_D_MCU: pad.7@2722.57,3124.75 U1.25 U9.1 | length 4055.5
  Top Layer w10: U1.25@657.23,2446.43 657.23,2460.06 699.45,2502.27 v1(699.45,2520.01) ; pad.7@2722.57,3124.75 2722.57,3091.55 2732.94,3081.18 U9.1@2768.08,3081.18
  Bottom Layer w20: v1(699.45,2520.01) 630.78,2520.01 603.46,2492.69 533.08,2492.69 378.12,2647.65 378.12,3234.94 844.54,3701.36 2351.95,3701.36 2723,3330.31 pad.7@2723,3124.75
SRC2_U1_IN_N: C28.2 R32.2 U9.4 | length 127.6
  Top Layer w10: U9.4@2826.35,3041.81 2826.35,2990.12 C28.2@2828.71,2987.75 2901.22,2987.75 R32.2@2901.28,2987.82
SRC2_U1_IN_P: C28.1 R31.2 U9.3 | length 150.5
  Top Layer w10: R31.2@2670.7,2988.94 2764.53,2988.94 C28.1@2765.72,2987.75 2768.08,2990.12 U9.3@2768.08,3041.81
SRC2_U2_AD: R22.2 R43.1 TP15.1 U6.5
SRC2_U2_AD_MCU: pad.7@2850.31,1698.27 U1.30 U11.1 | length 4070.7
  Top Layer w10: v1(558.45,2564.11) 575.27,2547.28 575.27,2480.47 558.81,2464.01 U1.30@558.81,2446.43 ; U11.1@2798.26,1715.32 2833.26,1715.32 pad.7@2850.31,1698.27
  Bottom Layer w20: v1(558.45,2564.11) 558.45,2973.71 675.81,3091.07 921.49,3091.07 1022.76,2989.81 2329.42,2989.81 2380.91,2938.33 2380.91,2349.12 2619.05,2110.98 2619.05,1755.95 2676.73,1698.27 pad.7@2850.31,1698.27
SRC2_U2_IN_N: C34.2 R42.2 U11.4 | length 119.5
  Top Layer w10: R42.2@2673.2,1808.68 2673.27,1808.74 C34.2@2737.63,1808.74 2739.99,1806.38 U11.4@2739.99,1754.69
SRC2_U2_IN_P: C34.1 R43.2 U11.3 | length 127.5
  Top Layer w10: U11.3@2798.26,1754.69 2798.26,1806.38 C34.1@2800.62,1808.74 2800.68,1808.8 R43.2@2873.03,1808.8
SRC2_U3_ADDA: R24.2 R51.1 TP18.1 U7.5
SRC2_U3_ADDA_MCU: pad.7@2851.77,326.17 U1.28 U13.1 | length 3633.4
  Top Layer w10: U1.28@598.18,2446.43 598.18,2458.12 619.75,2479.69 619.75,2547.83 v1(631.88,2559.96) ; U13.1@2798.26,357.16 2845.04,357.16 2851.77,350.42 pad.7@2851.77,326.17
  PWR w20: v1(631.88,2559.96) 710.61,2559.96 734.69,2535.88 734.69,2419.25 824.61,2329.33 824.61,2081.48 1743.9,1162.19 2094.21,1162.19 2446.25,810.14 2446.25,731.69 2768.99,408.95 2768.99,373.57 2816.4,326.17 pad.7@2851.77,326.17
SRC2_U3_IN_N: C40.2 R50.2 U13.4 | length 119.5
  Top Layer w10: R50.2@2673.2,450.51 2673.27,450.58 C40.2@2737.63,450.58 2739.99,448.22 U13.4@2739.99,396.53
SRC2_U3_IN_P: C40.1 R51.2 U13.3 | length 127.5
  Top Layer w10: U13.3@2798.26,396.53 2798.26,448.22 C40.1@2800.62,450.58 2800.68,450.64 R51.2@2873.03,450.64
Status1_U2_AD_MCU: J2.7 U1.7 | length 940.4
  Top Layer w10: v1(466.41,2135.44) 466.41,2288.1 481.05,2302.73 U1.7@493.85,2302.73
  Bottom Layer w20: v1(466.41,2135.44) 479.73,2148.75 696.82,2148.75 956.93,2408.86 J2.7@1107.37,2408.86
Status1_U3_ADDA_MCU: J2.11 U1.16 | length 747.3
  Top Layer w10: U1.16@657.23,2257.46 705.93,2257.46 906.2,2057.19 1143.47,2057.19 1157.37,2071.09 1157.37,2158.86 J2.11@1107.37,2208.86
Status1_U6_AD: J2.8 R15.1 R39.2 TP5.1 U6.2 | length 2864
  Top Layer w20: R39.2@2482.79,2101.58 v1(2527.03,2101.58) 2571.27,2101.58 2580.69,2092.16 U6.2@2661.92,2092.16
  Top Layer w30: J2.8@1207.37,2408.86 TP5.1@1581.99,2408.86 ; R15.1@1623.28,3407.98 v1(1673.96,3407.98)
  PWR w30: TP5.1@1581.99,2408.86 1677.49,2504.35 1677.49,2744.4 1539.06,2882.82 1539.06,3273.08 v1(1673.96,3407.98)
  Bottom Layer w30: TP5.1@1581.99,2408.86 2273.46,2408.86 2527.03,2155.29 v1(2527.03,2101.58)
Status1_U7_ADDA: J2.12 R17.1 R47.2 TP7.1 U7.2 | length 4352.9
  Top Layer w20: R47.2@2459.41,743.42 2547.89,743.42 2557.32,733.99 v1(2588.08,733.99) U7.2@2638.54,733.99
  Top Layer w30: J2.12@1207.37,2208.86 TP7.1@1581.99,2208.86 ; R17.1@1623.28,3189.52 v1(1673.96,3189.52)
  PWR w30: TP7.1@1581.99,2208.86 1777.05,2403.92 1777.05,2775.2 1629.71,2922.53 1629.71,3145.27 v1(1673.96,3189.52)
  Bottom Layer w30: TP7.1@1581.99,2208.86 1741.2,2049.65 1741.2,693.2 1908.66,525.74 2413.32,525.74 2588.08,700.5 v1(2588.08,733.99)
Status2_U2_AD_MCU: J2.9 U1.8 | length 860.3
  Top Layer w10: v1(493.85,2116.11) U1.8@493.85,2283.05
  Bottom Layer w20: v1(493.85,2116.11) 710.48,2116.11 903.22,2308.86 J2.9@1107.37,2308.86
Status2_U3_ADDA_MCU: J2.13 U1.17 | length 496.7
  Top Layer w10: U1.17@682.82,2283.05 720.71,2283.05 734.16,2269.6
  Top Layer w20: 734.16,2269.6 894.9,2108.86 J2.13@1107.37,2108.86
Status2_U6_AD: J2.10 R16.1 R41.2 TP6.1 U6.4 | length 3082.2
  Top Layer w20: R41.2@2482.79,1966.29 v1(2527.03,1966.29) 2552.43,1966.29 2578.3,1992.16 U6.4@2661.92,1992.16
  Top Layer w30: J2.10@1207.37,2308.86 TP6.1@1431.11,2308.86 ; R16.1@1623.28,3298.75 v1(1673.96,3298.75)
  PWR w30: TP6.1@1431.11,2308.86 1597.79,2308.86 1726.91,2437.98 1726.91,2762.57 1585.89,2903.59 1585.89,3210.67 v1(1673.96,3298.75)
  Bottom Layer w30: TP6.1@1431.11,2308.86 2312.8,2308.86 2483.83,2137.82 2483.83,2009.48 v1(2527.03,1966.29)
Status2_U7_ADDA: J2.14 R18.1 R49.2 TP8.1 U7.4 | length 4444.6
  Top Layer w20: R49.2@2459.41,608.12 2529.05,608.12 2554.92,633.99 v1(2588.08,633.99) U7.4@2638.54,633.99
  Top Layer w30: J2.14@1207.37,2108.86 TP8.1@1431.11,2108.86 ; R18.1@1623.28,3080.28 v1(1673.96,3080.28)
  PWR w30: TP8.1@1431.11,2108.86 1603.07,2108.86 1825.96,2331.75 1825.96,2789.81 1673.96,2941.8 v1(1673.96,3080.28)
  Bottom Layer w30: TP8.1@1431.11,2108.86 1597.71,2108.86 1697.86,2008.71 1697.86,666.47 1884.31,480.01 2434.09,480.01 v1(2588.08,633.99)
SWCLK: J1.4 U1.24 U2.4 | length 707.4
  Top Layer w10: U1.24@682.82,2420.84 697.59,2420.84 807.77,2531.03 v1(807.77,2569.45) J1.4@807.77,2641.37 ; v1(860.53,2955.58) U2.4@860.53,2974.11
  Bottom Layer w10: v1(807.77,2569.45) 807.77,2646.63 844.49,2683.35 844.49,2939.55 v1(860.53,2955.58)
SWDIO: J1.2 U1.23 U2.5 | length 795.7
  Top Layer w10: U1.23@682.82,2401.16 710.69,2401.16 857.77,2548.23 v1(857.77,2569.45) J1.2@857.77,2641.37 ; U2.5@860.53,2993.8 881.07,2993.8 v1(895.77,2979.09)
  Bottom Layer w10: v1(857.77,2569.45) 857.77,2641.37 878.52,2662.12 878.52,2922.78 895.77,2940.03 v1(895.77,2979.09)
VM: C12.2 C13.2 C14.2 C15.2 C17.2 C18.2 C19.2 D14.1 D15.1 D16.1 D17.1 D18.1 D19.1 J11.1 J12.1 J13.1 J14.1 J15.1 J16.1 L1.2 R6.2 TP16.1 TP20.1 TP22.1 TP24.1 TP26.1 TP28.1 TP30.1 U4.2 U4.3 | length 2302
  Top Layer w20: R6.2@939.58,2239.4 v1(987.48,2239.4)
  PWR w20: v1(987.48,2239.4) 987.48,2036.99 1204.79,1819.69 1705.63,1819.69 1804.99,1720.32 1804.99,1388.97 1892.15,1301.81 TP16.1@2540.59,1301.81
  other v1: 3724.29,95.04 3820.89,95.04 3917.48,95.04 4014.08,95.04 4110.67,95.04 4207.27,95.04 3724.29,160.63 3820.89,160.63 3918.3,160.63 4014.9,160.63 4111.5,160.63 4208.09,160.63 3724.29,226.23 3820.89,226.23 3917.48,226.23 4110.67,226.23 4207.27,226.23 3724.29,291.82 3820.89,291.82 3917.48,291.82 4014.08,291.82 4110.67,291.82 4207.27,291.82 3434.5,826.87 3531.1,826.87 3627.7,826.87 3725.11,826.87 3820.89,826.87 3917.48,826.87 4014.08,826.87 4110.67,826.87 4207.27,826.87 3435.33,892.46 3531.1,892.46 3725.11,892.46 3820.89,892.46 3918.3,892.46 4014.9,892.46 4111.5,892.46 4208.09,892.46 3725.11,958.05 3820.89,958.05 3917.48,958.05 4110.67,958.05 4207.27,958.05 3627.7,1023.65 3725.11,1023.65 3820.89,1023.65 3917.48,1023.65 4014.08,1023.65 4110.67,1023.65 4207.27,1023.65 2443.62,1410.06 2502.38,1410.06 2563.14,1410.06 3724.29,1453.21 3820.89,1453.21 3917.48,1453.21 4014.08,1453.21 4110.67,1453.21 4207.27,1453.21 2563.14,1463.94 2443.62,1466.57 2502.38,1466.57 2563.14,1517.83 3724.29,1518.8 3820.89,1518.8 3918.3,1518.8 4014.9,1518.8 4111.5,1518.8 4208.09,1518.8 2443.62,1520.45 2502.38,1520.45 2563.14,1571.71 2443.62,1574.33 2502.38,1574.33 3724.29,1584.39 3820.89,1584.39 3917.48,1584.39 4110.67,1584.39 4207.27,1584.39 2563.14,1625.59 2443.62,1628.22 2502.38,1628.22 3724.29,1649.98 3820.89,1649.98 3917.48,1649.98 4014.08,1649.98 4110.67,1649.98 4207.27,1649.98 2443.62,1682.1 2502.38,1682.1 3434.51,2185.03 3531.1,2185.03 3627.7,2185.03 3725.11,2185.03 3820.89,2185.03 3917.48,2185.03 4014.08,2185.03 4110.67,2185.03 4207.27,2185.03 3435.33,2250.63 3531.1,2250.63 3725.11,2250.63 3820.89,2250.63 3918.3,2250.63 4014.9,2250.63 4111.5,2250.63 4208.09,2250.63 3725.11,2316.22 3820.89,2316.22 3917.48,2316.22 4110.67,2316.22 4207.27,2316.22 3627.7,2381.81 3725.11,2381.81 3820.89,2381.81 3917.48,2381.81 4014.08,2381.81 4110.67,2381.81 4207.27,2381.81 2450.06,2480.45 2519.16,2480.45 2588.26,2480.45 2657.36,2480.45 2726.47,2480.45 2450.06,2537.76 2519.16,2537.76 2588.26,2537.76 2657.36,2537.76 2726.47,2537.76 3434.51,2770.45 3531.1,2770.45 3627.7,2770.45 3725.11,2770.45 3820.89,2770.45 3917.48,2770.45 4014.08,2770.45 4110.67,2770.45 4207.27,2770.45 3435.33,2836.05 3531.1,2836.05 3725.11,2836.05 3820.89,2836.05 3918.3,2836.05 4014.9,2836.05 4111.5,2836.05 4208.09,2836.05 3725.11,2901.64 3820.89,2901.64 3917.48,2901.64 4110.67,2901.64 4207.27,2901.64 3627.7,2967.23 3725.11,2967.23 3820.89,2967.23 3917.48,2967.23 4014.08,2967.23 4110.67,2967.23 4207.27,2967.23 3434.51,3423.03 3531.1,3423.03 3627.7,3423.03 3725.11,3423.03 3820.89,3423.03 3917.48,3423.03 4014.08,3423.03 4110.67,3423.03 4207.27,3423.03 3435.33,3488.62 3531.1,3488.62 3820.89,3488.62 3918.3,3488.62 4014.9,3488.62 4111.5,3488.62 4208.09,3488.62 3820.89,3554.22 3917.48,3554.22 4110.67,3554.22 4207.27,3554.22 3627.7,3619.81 3725.11,3619.81 3820.89,3619.81 3917.48,3619.81 4014.08,3619.81 4110.67,3619.81 4207.27,3619.81
  other v4: 2320.67,2686.25 2347.44,2686.25
VM_ADC: R5.2 R6.1 U1.19 | length 291.1
  Top Layer w10: U1.19@682.82,2322.42 697.27,2322.42 719.28,2300.41 810.93,2300.41 832.93,2322.42 R5.2@872.65,2322.42 R6.1@872.65,2239.4
VM_IN: C1.2 C2.2 D7.1 J4.1 Q1.1 Q1.2 Q1.3 TP10.1 U3.2 U3.5
pads on no net: FID1.1 FID2.1 FID3.1 J1.6 J1.8 MP1.0 MP2.0 MP3.0 MP4.0 Q1.9@1725.32,1101.29 Q1.9@1766.37,1112.91 Q1.9@1766.37,1158.18 Q1.9@1766.37,1203.46 Q1.9@1818.73,1112.91 Q1.9@1818.73,1158.18 Q1.9@1818.73,1163.5 Q1.9@1818.73,1203.46 Q1.9@1871.09,1112.91 Q1.9@1871.09,1158.18 Q1.9@1871.09,1203.46 Q1.9@1912.14,1101.29 SH1-J2-1.0 SH2-J2.0 SH3-J2.0 SH4-J2.0 SH5-J2.0 SH6-J2.0 SH7-J2.0 SH8-J2.0 SH-J5.0 SH-J6.0 SH-J7.0 SH-J8.0 SH-J9.0 SH-J10.0 U1.18 U1.27 U2.2 U3.3 U3.7 U4.7

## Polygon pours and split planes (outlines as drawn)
GND on Bottom Layer "NONET_L-01_P-001" (solid, remove dead copper, pour order 5): 26.27,144.45 146.43,24.29 4182.19,24.29 4274.78,116.88 4274.78,3912 4215.78,3971 142.58,3971 26.12,3854.54
BUCK_3V3 on Bottom Layer "NONET_L-01_P-001" (solid, remove dead copper, pour order 0): 2167.44,2903.17 2167.44,2928.98 2185.62,2947.16 2324.65,2947.16 2362.36,2909.45 2362.36,2449.61 2348.34,2435.69 2180.25,2435.69 2167.44,2448.5
VM on Bottom Layer "NONET_L-01_P-001" (solid, remove dead copper, pour order 2): 3233.36,24.95 3134.14,124.17 3134.14,723.77 2649.32,1208.59 2334.19,1208.59 2238.41,1303.13 2238.41,3832.68 2376.41,3970.68 4159.39,3970.68 4274.64,3855.44 4274.64,136.25 4159.28,24.95
GND on PWR "NONET_L-01_P-001" (solid, remove dead copper, pour order 13): 26.27,144.45 146.43,24.29 4160.65,24.29 4274.78,138.43 4274.78,3855.29 4159.07,3971 142.58,3971 26.12,3854.54
BUCK_3V3 on PWR "NONET_L-01_P-001" (solid, remove dead copper, pour order 9): 422.97,2474.68 459.25,2510.96 459.25,2650.14 522.21,2713.11 909.54,2713.11 964.93,2657.71 1142.19,2657.71 1156.18,2671.7 1156.18,3159.33 1079.27,3232.19 82.47,3232.19 25.84,3175.56 25.84,1737.2 33.27,1729.77 390.9,1729.77 422.97,1761.84
GND on GND "NONET_L-01_P-001" (solid, remove dead copper, pour order 14): 26.27,144.45 146.43,24.29 4160.65,24.29 4274.78,138.43 4274.78,3855.29 4159.07,3971 142.58,3971 26.12,3854.54
GND on Top Layer "NONET_L-01_P-001" (solid, remove dead copper, pour order 15): 26.27,144.45 146.43,24.29 4160.65,24.29 4274.78,138.43 4274.78,3855.29 4159.07,3971 142.58,3971 26.12,3854.54

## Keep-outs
Keep-Out Layer:
  lines w10: 0,0 4300,-0.91 4300.85,3999.09 0.85,4000 0,0.15
  text ".Layer_Name" at -287.12,-1133.2 h60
